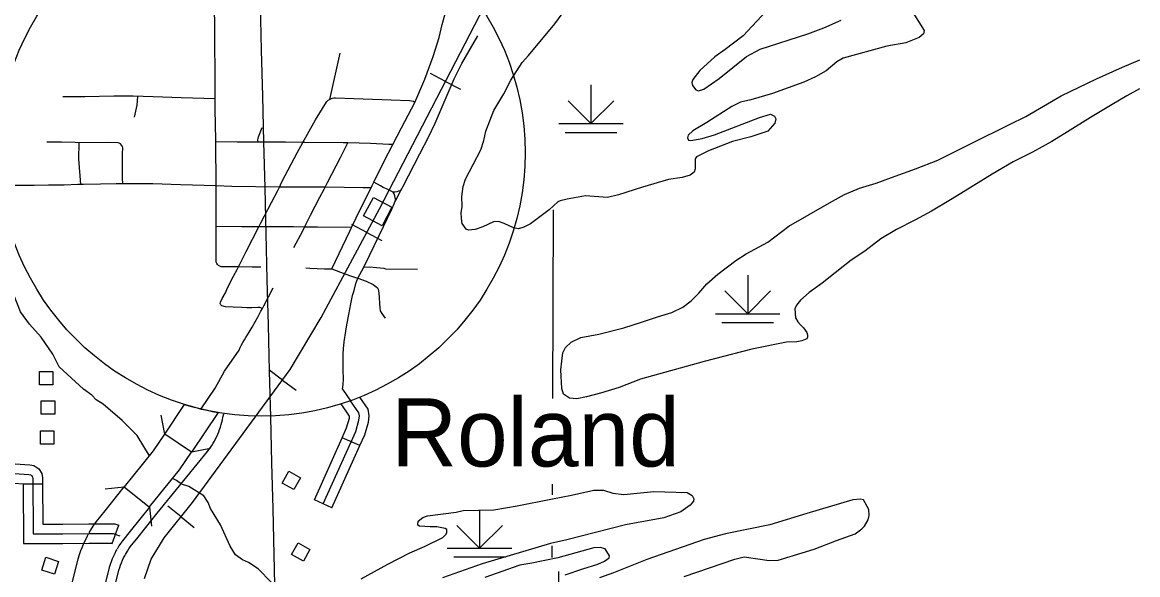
# Model space of a CAD drawing. Extents: x -19 to 366, y -4 to 359.
# Drawn here: x 141.61 to 143.248, y 201.221 to 202.033 of the extents above; entities that cross this region are included whole.
import ezdxf

# ---------------------------------------------------------------- set-up
doc = ezdxf.new("R2010")
doc.units = 0
for name, color, linetype in [('21', 7, 'Continuous'), ('Level 19', 7, 'Continuous'), ('R_Axis Annot', 7, 'Continuous'), ('R_Contour Annot', 7, 'Continuous'), ('R_Horz Alg Annot', 7, 'Continuous'), ('R_ROW', 7, 'Continuous'), ('R_ROW Annot', 7, 'Continuous'), ('R_Temp Easement', 7, 'Continuous'), ('R_Vert Alg', 7, 'Continuous'), ('R_Water Annot', 7, 'Continuous'), ('Sheet Fence', 7, 'Continuous'), ('T_Drafting', 7, 'Continuous'), ('T_Vehicle Path Lt Major', 7, 'Continuous')]:
    doc.layers.add(name, color=color, linetype=linetype)

msp = doc.modelspace()

# ---------------------------------------------------------------- linework, layer by layer
at = {"layer": '21'}
for points in [[(141.6351, 201.5001), (141.6351, 201.5198), (141.6549, 201.5198), (141.6549, 201.5001)], [(141.6378, 201.4572), (141.6378, 201.477), (141.6576, 201.477), (141.6576, 201.4572)], [(141.6366, 201.4131), (141.6366, 201.4328), (141.6564, 201.4328), (141.6564, 201.4131)], [(142.0185, 201.3638), (142.009, 201.3465), (141.9917, 201.356), (142.0012, 201.3733)], [(142.0151, 201.2682), (142.0323, 201.2587), (142.0228, 201.2413), (142.0055, 201.2509)], [(141.6573, 201.2221), (141.6385, 201.2282), (141.6446, 201.247), (141.6634, 201.2409)]]:
    msp.add_lwpolyline(points, close=True, dxfattribs=at)
at = {"layer": 'Level 19'}
msp.add_circle((141.9618, 201.841), 0.3866, dxfattribs=at)
at = {"layer": 'R_Axis Annot'}
for points in [[(142.3892, 201.4802), (142.3902, 201.7571)], [(142.3887, 201.3389), (142.3888, 201.3545)], [(142.3884, 201.2469), (142.3884, 201.2641)]]:
    msp.add_lwpolyline(points, dxfattribs=at)
at = {"layer": 'R_Contour Annot'}
for p, q in [((141.8584, 201.4014), (141.8191, 201.4278)), ((141.7598, 201.3504), (141.7967, 201.3208))]:
    msp.add_line(p, q, dxfattribs=at)
for points in [[(142.1866, 201.9151), (142.2012, 201.9489), (142.2135, 201.9822), (142.2223, 202.0102), (142.2264, 202.0293), (142.2312, 202.0449), (142.2344, 202.0629)], [(142.1543, 201.8532), (142.1671, 201.8779), (142.1866, 201.9151)], [(142.1262, 201.7979), (142.1419, 201.8295), (142.1543, 201.8532)], [(142.1222, 201.7898), (142.1237, 201.793), (142.1262, 201.7979)], [(142.0933, 201.7311), (142.1073, 201.7596), (142.1222, 201.7898)], [(142.0645, 201.6705), (142.0909, 201.7261), (142.0933, 201.7311)], [(142.0265, 201.672), (142.0323, 201.6717), (142.043, 201.6712), (142.0538, 201.6708), (142.0645, 201.6705)], [(141.9626, 201.6123), (141.9646, 201.6161), (141.9783, 201.6429)], [(141.8725, 201.4648), (141.8933, 201.4952), (141.907, 201.5203), (141.9284, 201.5511), (141.9302, 201.555), (141.9321, 201.5588), (141.9341, 201.5626), (141.9362, 201.5662), (141.9385, 201.5699), (141.943, 201.5774), (141.9475, 201.5851), (141.9519, 201.5928), (141.9562, 201.6005), (141.9605, 201.6083), (141.9626, 201.6123)], [(141.8191, 201.4278), (141.8484, 201.4713)], [(141.7616, 201.2513), (141.7644, 201.2561), (141.7664, 201.2593), (141.7686, 201.2624), (141.78, 201.2765), (141.8082, 201.3118), (141.8515, 201.3652), (141.8818, 201.4023), (141.884, 201.4053), (141.8862, 201.4083), (141.8883, 201.4114), (141.8902, 201.4145), (141.8921, 201.4178), (141.8939, 201.4211), (141.8955, 201.4244), (141.8971, 201.4278), (141.8985, 201.4312), (141.8998, 201.4347), (141.901, 201.4382), (141.9021, 201.4418), (141.9031, 201.4454), (141.904, 201.449), (141.9047, 201.4527), (141.9058, 201.4579)], [(141.8976, 201.4597), (141.8584, 201.4014)], [(141.7598, 201.3504), (141.76, 201.3506), (141.8028, 201.4034), (141.8191, 201.4278)], [(141.7967, 201.3208), (141.7968, 201.3209), (141.8409, 201.3753), (141.8584, 201.4014)], [(141.7083, 201.2829), (141.7117, 201.2887), (141.7151, 201.294), (141.7191, 201.2997), (141.7317, 201.3152), (141.7598, 201.3504)], [(141.7967, 201.3208), (141.7686, 201.2856), (141.757, 201.2712), (141.7544, 201.2675), (141.752, 201.2638), (141.7492, 201.259)], [(141.6796, 201.1954), (141.6922, 201.2449), (141.6941, 201.2512), (141.6961, 201.2569), (141.6983, 201.2624), (141.7006, 201.2679), (141.7031, 201.2733), (141.7059, 201.2786), (141.7074, 201.2815)], [(141.7488, 201.2584), (141.7476, 201.2563), (141.7457, 201.2525), (141.7438, 201.2485), (141.7421, 201.2446), (141.7406, 201.2405), (141.7391, 201.2364), (141.7378, 201.2322), (141.7256, 201.1843)], [(141.7398, 201.1808), (141.7519, 201.2282), (141.753, 201.2319), (141.7542, 201.2355), (141.7556, 201.2391), (141.7571, 201.2426), (141.7588, 201.246), (141.7605, 201.2494), (141.7616, 201.2513)]]:
    msp.add_lwpolyline(points, dxfattribs=at)
msp.add_arc((141.9618, 201.841), 0.3866, 252.944, 260.4453, dxfattribs=at)
at = {"layer": 'R_ROW'}
for p, q in [((142.0615, 201.9195), (142.0769, 201.9871)), ((141.6114, 201.3549), (141.6398, 201.355)), ((141.7422, 201.2673), (141.752, 201.294))]:
    msp.add_line(p, q, dxfattribs=at)
for points in [[(141.8933, 201.9201), (141.8932, 201.9325), (141.8931, 201.9497), (141.8931, 201.9708), (141.893, 201.9902), (141.8929, 202.0196), (141.8927, 202.0373), (141.8922, 202.0437)], [(142.166, 201.7857), (142.1672, 201.788), (142.1689, 201.7912), (142.194, 201.8394), (142.2071, 201.865), (142.2164, 201.8845), (142.2325, 201.9224), (142.2444, 201.9494), (142.2557, 201.9721), (142.279, 202.0127)], [(141.8933, 201.9201), (141.8431, 201.9216), (141.8024, 201.9232), (141.773, 201.924), (141.7513, 201.9244), (141.7445, 201.9243), (141.7019, 201.9233), (141.6697, 201.923)], [(141.8942, 201.857), (141.8942, 201.8601), (141.8938, 201.8821), (141.8934, 201.905), (141.8933, 201.9201)], [(142.022, 201.856), (142.0287, 201.8684), (142.0405, 201.8894), (142.0571, 201.9164), (142.0587, 201.9178)], [(142.0615, 201.9195), (142.0587, 201.9178)], [(142.1866, 201.9151), (142.1843, 201.9162), (142.1816, 201.917), (142.1787, 201.9173), (142.1515, 201.9184), (142.1243, 201.9194), (142.0971, 201.9202), (142.0699, 201.921), (142.0673, 201.9211), (142.0648, 201.9207), (142.0624, 201.92), (142.0615, 201.9195)], [(141.9566, 201.8565), (141.9561, 201.8601), (141.9562, 201.8621), (141.957, 201.8645), (141.9625, 201.878)], [(141.6933, 201.8557), (141.6874, 201.8561), (141.6677, 201.8565), (141.646, 201.8566)], [(141.6961, 201.7943), (141.6928, 201.8321), (141.6933, 201.8557)], [(141.7574, 201.7955), (141.7572, 201.8042), (141.7571, 201.813), (141.7571, 201.8218), (141.7572, 201.8306), (141.7573, 201.8394), (141.7576, 201.8481), (141.7571, 201.8503), (141.7559, 201.8523), (141.7544, 201.854), (141.7524, 201.8552), (141.7502, 201.8558), (141.7368, 201.8563), (141.6933, 201.8557)], [(141.8946, 201.7926), (141.8948, 201.8087), (141.8942, 201.8414), (141.8942, 201.857)], [(141.9566, 201.8565), (141.9254, 201.8567), (141.8942, 201.857)], [(142.022, 201.856), (141.9963, 201.8565), (141.9589, 201.8565), (141.9566, 201.8565)], [(141.9876, 201.7904), (141.9909, 201.7974), (141.9962, 201.8076), (142.0138, 201.8411), (142.022, 201.856)], [(142.0879, 201.8555), (142.0813, 201.8556), (142.0247, 201.856), (142.022, 201.856)], [(142.0547, 201.7906), (142.0582, 201.7972), (142.0773, 201.8341), (142.0879, 201.8555)], [(142.1543, 201.8532), (142.1485, 201.8532), (142.1214, 201.8548), (142.0879, 201.8555)], [(141.7574, 201.7955), (141.7478, 201.7953), (141.7249, 201.795), (141.7001, 201.7944), (141.6961, 201.7943)], [(141.8946, 201.7926), (141.8424, 201.7942), (141.8015, 201.7952), (141.7881, 201.7955), (141.7747, 201.7956), (141.7612, 201.7955), (141.7574, 201.7955)], [(142.1545, 201.7833), (142.145, 201.7879), (142.1399, 201.7903), (142.136, 201.7923), (142.1262, 201.7979)], [(141.6961, 201.7943), (141.6917, 201.7943), (141.6715, 201.7935), (141.6486, 201.7933), (141.6275, 201.793), (141.6038, 201.7931), (141.5781, 201.7931)], [(141.8947, 201.7327), (141.8945, 201.7611), (141.8945, 201.7806), (141.8945, 201.783), (141.8945, 201.7891), (141.8946, 201.7926)], [(141.9876, 201.7904), (141.9178, 201.7917), (141.8946, 201.7926)], [(141.9575, 201.7324), (141.9605, 201.7383), (141.976, 201.7681), (141.9852, 201.7857), (141.9876, 201.7904)], [(142.0547, 201.7906), (141.9876, 201.7904)], [(142.0245, 201.732), (142.0331, 201.7496), (142.0468, 201.7758), (142.0532, 201.7877), (142.0547, 201.7906)], [(142.1222, 201.7898), (142.1105, 201.7895), (142.0547, 201.7906)], [(142.166, 201.7857), (142.1627, 201.7848), (142.16, 201.7838), (142.1573, 201.7833), (142.1545, 201.7833)], [(142.1586, 201.7714), (142.1574, 201.775), (142.1569, 201.7779), (142.1559, 201.7807), (142.1545, 201.7833)], [(142.1586, 201.7714), (142.166, 201.7857)], [(142.1117, 201.6732), (142.1199, 201.6901), (142.1339, 201.7198), (142.1525, 201.7584), (142.156, 201.7663), (142.1573, 201.7689), (142.1586, 201.7714)], [(141.8967, 201.6768), (141.8956, 201.6785), (141.8949, 201.6805), (141.8946, 201.6826), (141.8945, 201.709), (141.8947, 201.7327)], [(141.9575, 201.7324), (141.9324, 201.7324), (141.8947, 201.7327)], [(141.9273, 201.6735), (141.9387, 201.6963), (141.9575, 201.7324)], [(142.0245, 201.732), (142.0085, 201.7322), (141.9602, 201.7324), (141.9575, 201.7324)], [(142.0087, 201.7018), (142.0218, 201.7266), (142.0245, 201.732)], [(142.0933, 201.7311), (142.0433, 201.7318), (142.0245, 201.732)], [(141.9273, 201.6735), (141.9043, 201.6737), (141.9022, 201.6738), (141.9001, 201.6743), (141.8983, 201.6753), (141.8967, 201.6768)], [(141.9014, 201.6176), (141.9007, 201.6199), (141.9012, 201.6218), (141.9034, 201.6271), (141.9082, 201.6355), (141.9115, 201.6425), (141.9204, 201.6597), (141.9257, 201.6694), (141.9273, 201.6735)], [(141.9602, 201.6732), (141.9474, 201.6733), (141.9273, 201.6735)], [(142.0645, 201.6705), (142.0773, 201.6659), (142.0905, 201.6608), (142.0992, 201.6579), (142.1026, 201.6567)], [(142.1026, 201.6567), (142.1117, 201.6732)], [(142.1117, 201.6732), (142.1199, 201.6734), (142.13, 201.6726), (142.1409, 201.6715), (142.1435, 201.6708), (142.1902, 201.6702)], [(142.0804, 201.494), (142.0811, 201.5008), (142.0815, 201.5087), (142.0813, 201.5223), (142.0811, 201.537), (142.081, 201.5456), (142.0818, 201.5531), (142.0828, 201.5632), (142.0851, 201.5791), (142.0865, 201.5883), (142.0895, 201.6038), (142.0924, 201.6193), (142.0948, 201.6313), (142.0973, 201.639), (142.1, 201.6491), (142.1026, 201.6567)], [(142.1026, 201.6567), (142.1152, 201.6526), (142.1252, 201.6475), (142.1292, 201.6446), (142.1317, 201.6427), (142.1326, 201.6408), (142.1334, 201.6355), (142.1349, 201.6131), (142.1356, 201.6089), (142.1379, 201.6048), (142.1431, 201.5982)], [(141.9626, 201.6123), (141.9587, 201.6139), (141.956, 201.6137), (141.9471, 201.6132), (141.9397, 201.6133), (141.9325, 201.6137), (141.9198, 201.6144), (141.9085, 201.6147), (141.9028, 201.6161), (141.9014, 201.6176)], [(141.5354, 201.3947), (141.5513, 201.3918), (141.5784, 201.385), (141.5995, 201.3842), (141.6212, 201.3827), (141.6271, 201.3817), (141.6342, 201.3771), (141.6387, 201.3701), (141.6398, 201.3637), (141.6398, 201.36), (141.6398, 201.355)], [(141.5483, 201.3779), (141.5764, 201.3708), (141.5987, 201.37), (141.6196, 201.3685), (141.6219, 201.3682), (141.6239, 201.3669), (141.6252, 201.3649), (141.6256, 201.3625), (141.6258, 201.2814), (141.6312, 201.2814), (141.6695, 201.2817), (141.7076, 201.2821), (141.7436, 201.2819), (141.7532, 201.2784)], [(141.5303, 201.3668), (141.5453, 201.364), (141.5743, 201.3567), (141.598, 201.3558), (141.6114, 201.3549)], [(141.6114, 201.3549), (141.6117, 201.2673), (141.6313, 201.2672), (141.6475, 201.2673)], [(141.6398, 201.355), (141.64, 201.2957), (141.6472, 201.2958)], [(141.6472, 201.2958), (141.6694, 201.2959), (141.7075, 201.2963), (141.7461, 201.2961), (141.752, 201.294)], [(141.6475, 201.2673), (141.6697, 201.2675), (141.7076, 201.2679), (141.741, 201.2677), (141.7422, 201.2673)]]:
    msp.add_lwpolyline(points, dxfattribs=at)
at = {"layer": 'R_ROW Annot'}
for p, q in [((142.1057, 201.411), (142.0798, 201.4226)), ((142.0648, 201.3197), (142.0389, 201.3313))]:
    msp.add_line(p, q, dxfattribs=at)
for points in [[(141.779, 201.9238), (141.7782, 201.9112), (141.7743, 201.8934)], [(142.0804, 201.494), (142.0922, 201.477)], [(142.0518, 201.3255), (142.0996, 201.432), (142.1044, 201.4484), (142.105, 201.4546), (142.1044, 201.4593), (142.0922, 201.477)], [(142.0798, 201.4226), (142.0862, 201.4369), (142.0904, 201.4512), (142.0907, 201.4541), (142.0782, 201.4722)], [(142.1057, 201.411), (142.1129, 201.4271), (142.1183, 201.4456), (142.1194, 201.4548), (142.1179, 201.4647), (142.1059, 201.4822)], [(142.0389, 201.3313), (142.0798, 201.4226)], [(142.0648, 201.3197), (142.1057, 201.411)]]:
    msp.add_lwpolyline(points, dxfattribs=at)
at = {"layer": 'R_Temp Easement'}
for points in [[(141.7186, 201.4781), (141.7122, 201.4851), (141.6999, 201.4937), (141.664, 201.5267), (141.655, 201.5453), (141.6376, 201.5705), (141.6207, 201.5892), (141.6075, 201.6074), (141.5923, 201.6461), (141.5855, 201.677), (141.5816, 201.6901), (141.5562, 201.7284), (141.532, 201.7509), (141.5098, 201.7759)], [(141.7968, 201.396), (141.7787, 201.4258), (141.7567, 201.4481), (141.7286, 201.472), (141.7186, 201.4781)], [(141.9755, 201.2103), (141.9563, 201.2302), (141.9423, 201.2393), (141.9332, 201.2431), (141.923, 201.2507), (141.9154, 201.2632), (141.901, 201.2947), (141.8866, 201.3186), (141.8828, 201.3273), (141.8768, 201.3372), (141.8545, 201.3512), (141.8439, 201.3546), (141.8363, 201.3599), (141.8308, 201.3628)]]:
    msp.add_lwpolyline(points, dxfattribs=at)
at = {"layer": 'R_Vert Alg'}
for points in [[(141.8191, 201.4278), (141.8137, 201.4557)], [(141.8863, 201.4068), (141.8584, 201.4014)], [(141.7316, 201.3474), (141.7598, 201.3504)], [(141.7967, 201.3207), (141.7997, 201.2925)]]:
    msp.add_lwpolyline(points, dxfattribs=at)
at = {"layer": 'R_Water Annot'}
for p, q in [((142.2315, 201.9459), (142.2093, 201.9574)), ((142.2315, 201.9459), (142.2537, 201.9344)), ((142.1161, 201.7241), (142.094, 201.7359)), ((142.1161, 201.7241), (142.1381, 201.7123)), ((141.9921, 201.5073), (141.9719, 201.5221)), ((141.9921, 201.5073), (142.0122, 201.4925)), ((141.8431, 201.3065), (141.8236, 201.3222)), ((141.8431, 201.3065), (141.8625, 201.2908))]:
    msp.add_line(p, q, dxfattribs=at)
msp.add_lwpolyline([(141.7894, 201.2159), (141.7992, 201.2441), (141.8182, 201.2758), (141.8598, 201.3273), (142.0036, 201.5229), (142.049, 201.5991), (142.1346, 201.7588), (142.3936, 202.259)], dxfattribs=at)
msp.add_lwpolyline([(141.7894, 201.2159), (141.7992, 201.2441), (141.8182, 201.2758), (141.8598, 201.3273), (142.0036, 201.5229), (142.049, 201.5991), (142.1346, 201.7588), (142.3936, 202.259)], dxfattribs=at)
msp.add_lwpolyline([(142.1256, 201.7756), (142.1529, 201.7611), (142.1384, 201.7338), (142.1111, 201.7483)], close=True, dxfattribs=at)
at = {"layer": 'Sheet Fence'}
for points in [[(146.7783, 1.697), (146.5788, 10.3131), (146.3785, 18.9294), (146.1776, 27.5458), (145.9759, 36.1624), (145.7736, 44.7791), (145.5705, 53.396), (145.3668, 62.013), (145.1624, 70.6301), (144.9572, 79.2474), (144.7514, 87.8648), (144.5449, 96.4823), (144.3377, 105.1), (144.1299, 113.7179), (143.9213, 122.3359), (143.712, 130.954), (143.5021, 139.5723), (143.2915, 148.1907), (143.0802, 156.8092), (142.8682, 165.4279), (142.6555, 174.0468), (142.4422, 182.6658), (142.2282, 191.2849), (142.0135, 199.9042), (141.7981, 208.5236), (141.582, 217.1432), (141.3653, 225.7629), (141.1479, 234.3828), (140.9298, 243.0028), (140.711, 251.623), (140.4916, 260.2433), (140.2715, 268.8638), (140.0508, 277.4844), (139.8293, 286.1051), (139.6072, 294.726), (139.3845, 303.3471), (139.161, 311.9683), (138.937, 320.5896), (138.7122, 329.2111), (138.4868, 337.8328), (138.2607, 346.4546)], [(0, 198.1326), (7.1014, 198.137), (14.2028, 198.1503), (21.3042, 198.1724), (28.4055, 198.2034), (35.5068, 198.2433), (42.6081, 198.292), (49.7092, 198.3496), (56.8103, 198.4161), (63.9113, 198.4913), (71.0123, 198.5755), (78.1131, 198.6685), (85.2137, 198.7704), (92.3143, 198.8811), (99.4147, 199.0007), (106.5149, 199.1291), (113.615, 199.2664), (120.7149, 199.4126), (127.8146, 199.5676), (134.9141, 199.7315), (142.0135, 199.9042), (149.1125, 200.0858), (156.2114, 200.2762), (163.31, 200.4755), (170.4084, 200.6837), (177.5065, 200.9007), (184.6043, 201.1265), (191.7018, 201.3612), (198.799, 201.6048), (205.896, 201.8572), (212.9926, 202.1185), (220.0888, 202.3886), (227.1848, 202.6676), (234.2803, 202.9554), (241.3755, 203.2521), (248.4704, 203.5576), (255.5648, 203.872), (262.6589, 204.1952), (269.7525, 204.5273), (276.8457, 204.8682), (283.9385, 205.218), (291.0309, 205.5766), (298.1228, 205.9441), (305.2142, 206.3204), (312.3051, 206.7056), (319.3956, 207.0996), (326.4856, 207.5024), (333.5751, 207.9141), (340.664, 208.3347)]]:
    msp.add_spline(points, degree=3, dxfattribs=at)
at = {"layer": 'T_Drafting'}
for p, q in [((142.4452, 201.9407), (142.4452, 201.8838)), ((142.4452, 201.8838), (142.4117, 201.9173)), ((142.4452, 201.8838), (142.4787, 201.9173)), ((142.3978, 201.8838), (142.4925, 201.8838)), ((142.4073, 201.8709), (142.4831, 201.8709)), ((142.6754, 201.6615), (142.6754, 201.6047)), ((142.6754, 201.6047), (142.6419, 201.6382)), ((142.6754, 201.6047), (142.7089, 201.6382)), ((142.628, 201.6047), (142.7227, 201.6047)), ((142.6375, 201.5918), (142.7133, 201.5918)), ((142.2815, 201.3161), (142.2815, 201.2604)), ((142.2815, 201.2604), (142.248, 201.2939)), ((142.2815, 201.2604), (142.315, 201.2939)), ((142.2342, 201.2604), (142.3289, 201.2604)), ((142.2436, 201.2475), (142.3194, 201.2475)), ((142.3975, 201.2263), (142.3975, 201.1695))]:
    msp.add_line(p, q, dxfattribs=at)
at = {"layer": 'T_Vehicle Path Lt Major'}
for points in [[(142.3563, 201.7366), (142.3468, 201.7319), (142.3389, 201.7294), (142.3313, 201.7307), (142.3176, 201.7373), (142.3096, 201.7403), (142.3022, 201.7395), (142.2865, 201.7324), (142.275, 201.7283), (142.2652, 201.7274), (142.2617, 201.729), (142.2561, 201.7374), (142.2548, 201.7444), (142.2547, 201.7533), (142.256, 201.7615), (142.2557, 201.7768), (142.2577, 201.7917), (142.2611, 201.8024), (142.2835, 201.8454), (142.2878, 201.859), (142.2906, 201.8727), (142.3024, 201.9031), (142.3174, 201.9274), (142.3277, 201.9476), (142.344, 201.9737), (142.3536, 201.9837), (142.3921, 202.0304), (142.412, 202.0577)], [(142.9155, 202.0509), (142.9345, 202.0205), (142.9333, 202.0159), (142.9274, 202.0104), (142.9074, 202.0023), (142.8798, 201.9976), (142.8157, 201.98), (142.806, 201.9744), (142.7906, 201.9616), (142.775, 201.9526), (142.7578, 201.9449), (142.7118, 201.9279), (142.6798, 201.9186), (142.665, 201.9154), (142.6521, 201.9091), (142.6152, 201.8856), (142.5949, 201.8731), (142.5879, 201.8668), (142.5869, 201.8628), (142.5885, 201.8598), (142.592, 201.8589), (142.6086, 201.8621), (142.6266, 201.8672), (142.6928, 201.8927), (142.709, 201.8975), (142.7149, 201.8946), (142.7168, 201.8909), (142.7154, 201.8846), (142.705, 201.8729), (142.6798, 201.8644), (142.6531, 201.8575), (142.6177, 201.8441), (142.6001, 201.8349), (142.5983, 201.832), (142.5982, 201.8176), (142.5966, 201.8128), (142.5909, 201.8081), (142.5792, 201.8049), (142.5588, 201.8016), (142.5207, 201.7904), (142.4854, 201.7791), (142.4692, 201.7756), (142.437, 201.7777)], [(142.7018, 202.0483), (142.6686, 202.0126), (142.6424, 201.9929), (142.627, 201.9818), (142.6051, 201.962), (142.5947, 201.9487), (142.5931, 201.944), (142.5942, 201.94), (142.5991, 201.9333), (142.6032, 201.9321), (142.6107, 201.9344), (142.6333, 201.9499), (142.6737, 201.9826), (142.6936, 201.9932), (142.7635, 202.0158), (142.787, 202.0243), (142.8128, 202.0359)], [(142.7358, 201.7333), (142.7957, 201.7676), (142.8175, 201.7799), (142.8397, 201.7889), (142.8639, 201.7963), (142.8863, 201.8047), (142.9218, 201.8174), (142.9544, 201.83), (142.9818, 201.8437), (143.0033, 201.8547), (143.0597, 201.8825), (143.0838, 201.8943), (143.1357, 201.9248), (143.1878, 201.9495), (143.2258, 201.9667), (143.2511, 201.9777)], [(143.2509, 201.9349), (143.2319, 201.9246), (143.2106, 201.9118), (143.1789, 201.8927), (143.1451, 201.8718), (143.1218, 201.8577), (143.0938, 201.842), (143.0654, 201.8278), (143.0346, 201.8096), (143.0072, 201.7928), (142.973, 201.7719), (142.9451, 201.7553), (142.921, 201.7423), (142.8937, 201.7284), (142.8708, 201.7145), (142.8472, 201.6964), (142.8271, 201.6833), (142.8038, 201.6647), (142.7849, 201.6495), (142.7656, 201.6357), (142.7528, 201.6246), (142.7469, 201.6173), (142.7447, 201.612), (142.7455, 201.5985), (142.749, 201.5926), (142.7531, 201.5883), (142.7575, 201.5838), (142.762, 201.5773), (142.7634, 201.5735), (142.7631, 201.5704), (142.7622, 201.5676), (142.7546, 201.5648), (142.7473, 201.5633), (142.7323, 201.5631), (142.6816, 201.5529), (142.6113, 201.5346), (142.5179, 201.5085), (142.4864, 201.4964), (142.459, 201.4879), (142.4386, 201.4827), (142.4244, 201.4799), (142.4136, 201.4809), (142.4046, 201.4868), (142.4025, 201.4948), (142.4009, 201.5221), (142.4024, 201.5349), (142.4037, 201.5475), (142.4077, 201.555), (142.4159, 201.5631), (142.4303, 201.5698), (142.4565, 201.5748), (142.4934, 201.5838), (142.5209, 201.5928), (142.543, 201.6), (142.564, 201.6066), (142.5803, 201.6143), (142.5921, 201.6237), (142.6035, 201.6351), (142.6154, 201.6484), (142.6315, 201.6629), (142.6581, 201.6828), (142.6733, 201.6927), (142.7047, 201.7096), (142.7358, 201.7333)], [(142.437, 201.7777), (142.4104, 201.7727), (142.3997, 201.7703), (142.3965, 201.7689), (142.3836, 201.7575), (142.3563, 201.7366)], [(142.3366, 201.3226), (142.3862, 201.3324), (142.4166, 201.3381), (142.4492, 201.3457), (142.4634, 201.3455), (142.4772, 201.3414), (142.4934, 201.3394), (142.5375, 201.3437), (142.5863, 201.3423), (142.5938, 201.338), (142.5963, 201.333), (142.5956, 201.3293), (142.5907, 201.3237), (142.5771, 201.314), (142.5522, 201.3051), (142.4961, 201.2945), (142.4099, 201.2726), (142.3856, 201.2675), (142.2852, 201.2372), (142.2272, 201.2171)], [(142.1466, 201.2367), (142.1789, 201.2534), (142.2006, 201.2628), (142.2277, 201.2763), (142.2325, 201.281), (142.2335, 201.2835), (142.2336, 201.2878), (142.2309, 201.2895), (142.2188, 201.2918), (142.2088, 201.2917), (142.1932, 201.2925), (142.1911, 201.2942), (142.1914, 201.3001), (142.1983, 201.3054), (142.2051, 201.3077), (142.2472, 201.3135), (142.2575, 201.3159), (142.3027, 201.3166), (142.3366, 201.3226)], [(142.5818, 201.2187), (142.6563, 201.2441), (142.6701, 201.2475), (142.7067, 201.2425), (142.7203, 201.2429), (142.7731, 201.2591), (142.8057, 201.2717), (142.8331, 201.2816), (142.8431, 201.2887), (142.8468, 201.2926), (142.8524, 201.3019), (142.8535, 201.3084), (142.8533, 201.3171), (142.8452, 201.3315), (142.8412, 201.3323), (142.8295, 201.3312), (142.7624, 201.3112), (142.7077, 201.2949), (142.6426, 201.2816), (142.6116, 201.2731), (142.5271, 201.2438), (142.4784, 201.2244), (142.4578, 201.2171)], [(142.4072, 201.2211), (142.4331, 201.23), (142.4554, 201.2368), (142.4648, 201.2414), (142.472, 201.2464), (142.4723, 201.2494), (142.4661, 201.2597), (142.4587, 201.2615), (142.4494, 201.2607), (142.3967, 201.246), (142.3581, 201.2384), (142.3405, 201.2354), (142.2891, 201.2174)], [(142.1079, 201.2154), (142.1466, 201.2367)]]:
    msp.add_lwpolyline(points, dxfattribs=at)

# ---------------------------------------------------------------- texts
at = {"layer": 'R_Horz Alg Annot'}
msp.add_text('Roland', height=0.1, dxfattribs=at).set_placement((142.1519, 201.3804))

doc.saveas('drawing.dxf')
